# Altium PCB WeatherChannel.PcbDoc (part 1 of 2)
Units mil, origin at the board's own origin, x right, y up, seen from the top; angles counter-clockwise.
Board outline 4050 x 7300 mil, 2 copper layers (Top Layer, Bottom Layer); 129 components, 144 nets, 770 pads, 170 vias.
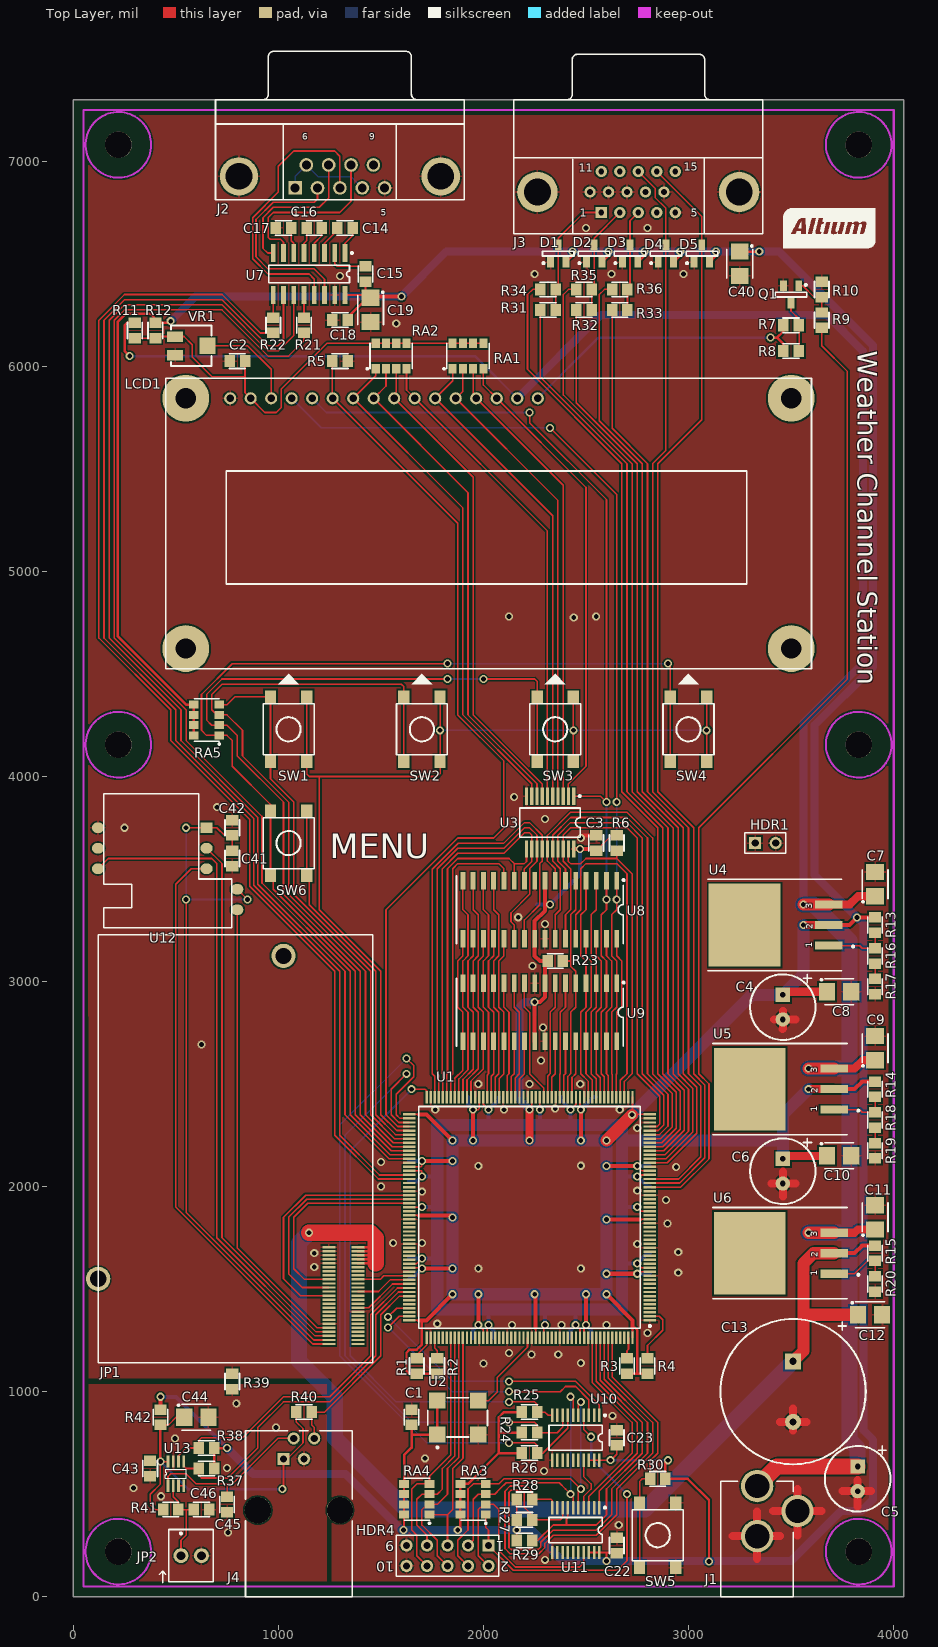
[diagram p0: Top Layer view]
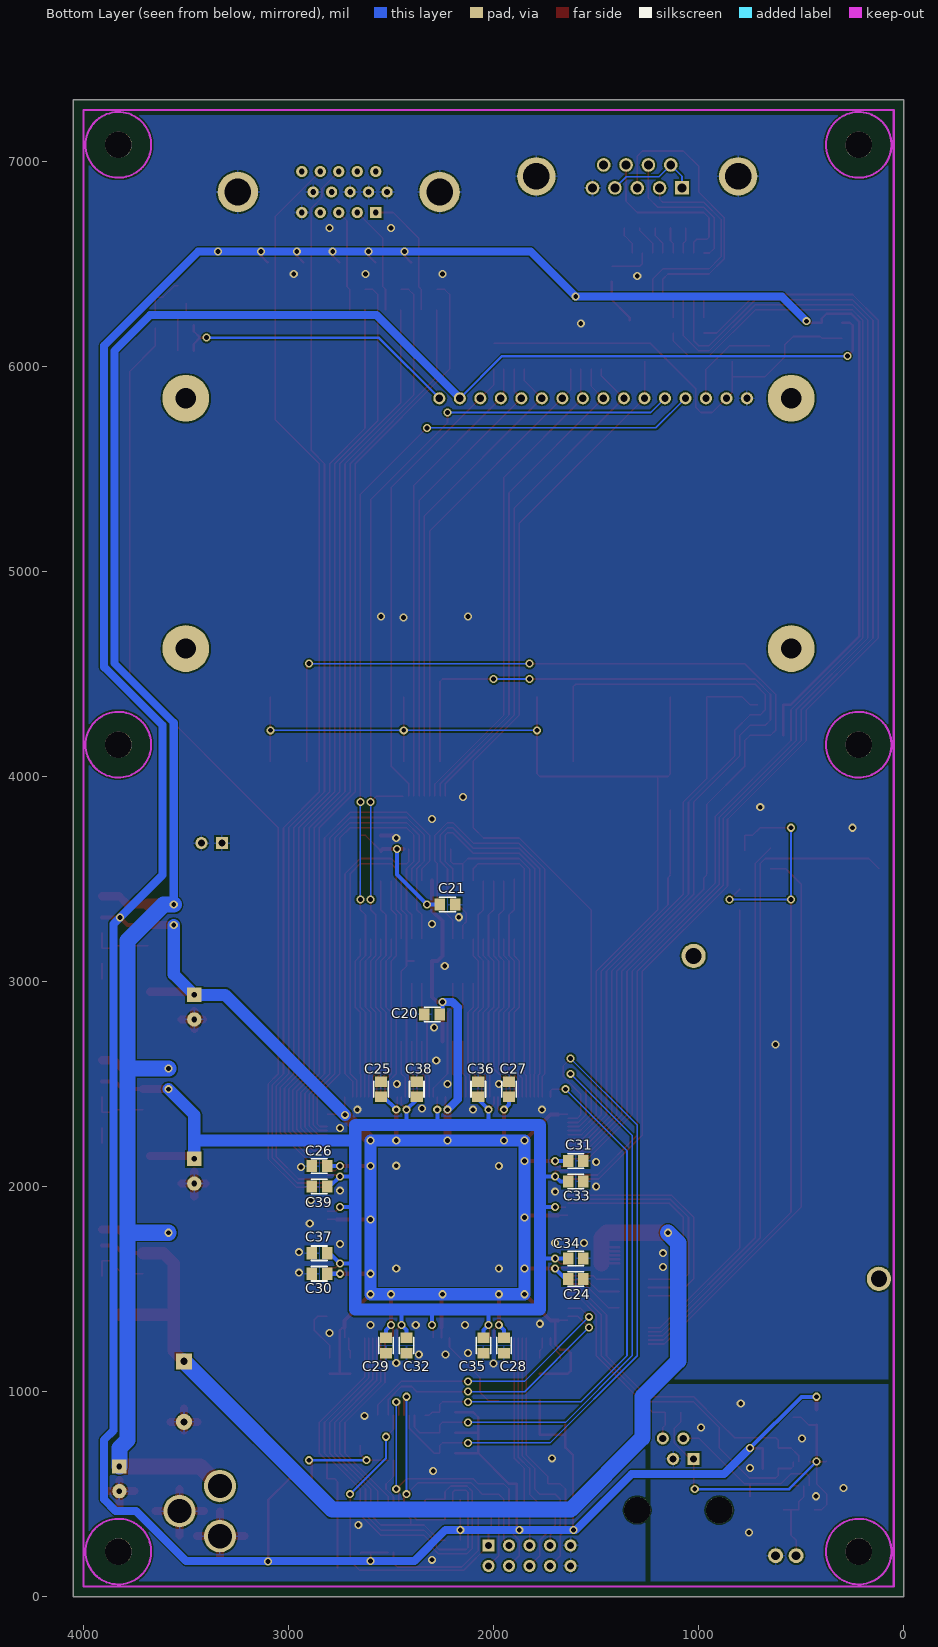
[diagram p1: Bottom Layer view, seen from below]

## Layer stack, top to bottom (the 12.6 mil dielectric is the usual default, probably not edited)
Top Layer: signal copper 1.4
Dielectric: dielectric 12.6, FR-4, Dk 4.8
Bottom Layer: signal copper 1.4

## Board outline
0,0 4050,0 4050,7300 0,7300

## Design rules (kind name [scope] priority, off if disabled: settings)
Clearance [All] p1: gap=7.87
FabricationTestPointUsage TestPointUsage [All] p1: valid=0 allowmultiple=FALSE
FabricationTestpoint Testpoint [All] p1: side=3 testpointundercomponent=TRUE minsize=40 maxsize=100 preferedsize=60 minholesize=0 maxholesize=40 preferedholesize=32 testpointgrid=1 allowsidetop=TRUE allowsidebottom=TRUE usegrid=TRUE gridtolerance=0.01
HoleSize [All] p1: absolutevalues=TRUE maxlimit=157.48 minlimit=1 maxpercent=80.000 minpercent=20.000
PolygonConnect [All] p1: connectstyle=Relief reliefconductorwidth=10 reliefentries=4 polygonreliefangle="90 Angle"
RoomDefinition U_WC_MODEM [InComponentClass('U_WC_MODEM')] p1: confinementstyle=ConfineIn formatcopy=TRUE lockcomponents=FALSE outline 50,1050 1525,1050 1525,4050 50,4050
RoomDefinition FPGA_U1_Manual [InComponentClass('FPGA_U1_Manual')] p2: confinementstyle=ConfineIn formatcopy=TRUE lockcomponents=FALSE outline 1450,625 2900,625 2900,1325 1450,1325
RoomDefinition U_FPGA_U1_Auto [InComponentClass('U_FPGA_U1_Auto')] p3: confinementstyle=ConfineIn formatcopy=TRUE lockcomponents=FALSE outline 1580,1160 2860,1160 2860,2540 1580,2540
RoomDefinition U_WC_Boot [InComponentClass('U_WC_Boot')] p4: confinementstyle=ConfineIn formatcopy=TRUE lockcomponents=FALSE outline 1450,1025 1450,25 2850,25 2850,1025
RoomDefinition U_WC_KB [InComponentClass('U_WC_KB')] p5: confinementstyle=ConfineIn formatcopy=TRUE lockcomponents=FALSE outline 50,3450 3250,3450 3250,4455 50,4455
RoomDefinition U_WC_LCD [InComponentClass('U_WC_LCD')] p6: confinementstyle=ConfineIn formatcopy=TRUE lockcomponents=FALSE outline 100,3550 4100,3550 4100,6525 100,6525
RoomDefinition U_WC_PWR [InComponentClass('U_WC_PWR')] p7: confinementstyle=ConfineIn formatcopy=TRUE lockcomponents=FALSE outline 4125,-200 4125,3850 3085,3850 3085,-200
RoomDefinition U_WC_RS232 [InComponentClass('U_WC_RS232')] p8: confinementstyle=ConfineIn formatcopy=TRUE lockcomponents=FALSE outline 2025,7625 350,7625 350,6100 2025,6100
RoomDefinition U_WC_SENS [InComponentClass('U_WC_SENS')] p9: confinementstyle=ConfineIn formatcopy=TRUE lockcomponents=FALSE outline 325,-25 1425,-25 1425,1125 325,1125
RoomDefinition U_WC_SRAM [InComponentClass('U_WC_SRAM')] p10: confinementstyle=ConfineIn formatcopy=TRUE lockcomponents=FALSE outline 2850,2550 2850,3550 1750,3550 1750,2550
RoomDefinition U_WC_VGA [InComponentClass('U_WC_VGA')] p11: confinementstyle=ConfineIn formatcopy=TRUE lockcomponents=FALSE outline 3375,7575 2065,7575 2065,6150 3375,6150
RoutingVias [All] p1: holewidth=23.62 width=39.37 viastyle="Through Hole" minholewidth=23.62 minwidth=39.37 maxholewidth=23.62 maxwidth=39.37
SilkscreenOverComponentPads [All] p1: minsilkscreentomaskgap=10
SolderMaskExpansion [All] p1: expansion=4
Width Width_Power [(InNet('1V8') OR InNet('4V1') OR InNet('VCC') OR InNet('5V') OR InNet('GND'))] p1: maxlimit=98.43 minlimit=7.87 preferedwidth=7.87
Width [All] p2: maxlimit=11.81 minlimit=7.87 preferedwidth=7.87
24 further rules are at their usual default settings.

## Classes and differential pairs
component class U_WC_Boot: C22 C23 HDR4 R24 R25 R26 R27 R28 R29 RA3 RA4 U10 U11
component class U_FPGA_U1_Auto: U1
net class RED[1..0]: RED0 RED1
net class RAM_ADDR[16..0]: RAM_ADDR0 RAM_ADDR1 RAM_ADDR2 RAM_ADDR3 RAM_ADDR4 RAM_ADDR5 RAM_ADDR6 RAM_ADDR7 RAM_ADDR8 RAM_ADDR9 RAM_ADDR10 RAM_ADDR11 RAM_ADDR12 RAM_ADDR13 RAM_ADDR14 RAM_ADDR15 RAM_ADDR16
net class RAM1_DATA[7..0]: RAM1_DATA0 RAM1_DATA1 RAM1_DATA2 RAM1_DATA3 RAM1_DATA4 RAM1_DATA5 RAM1_DATA6 RAM1_DATA7
net class RAM0_DATA[7..0]: RAM0_DATA0 RAM0_DATA1 RAM0_DATA2 RAM0_DATA3 RAM0_DATA4 RAM0_DATA5 RAM0_DATA6 RAM0_DATA7
net class KP_ROW[3..0]: KP_ROW0 KP_ROW1 KP_ROW2 KP_ROW3
net class KP_COL[3..0]: KP_COL0 KP_COL1 KP_COL2 KP_COL3
net class GREEN[1..0]: GREEN0 GREEN1
net class BLUE[1..0]: BLUE0 BLUE1
component class U_WC_VGA: C40 D1 D2 D3 D4 D5 J3 R31 R32 R33 R34 R35 R36
component class U_WC_SRAM: C20 C21 R23 U8 U9
component class U_WC_SENS: C43 C44 C45 C46 J4 JP2 R37 R38 R39 R40 R41 R42 U13
component class U_WC_RS232: C14 C15 C16 C17 C18 C19 J2 R21 R22 U7
component class U_WC_PWR: C4 C5 C6 C7 C8 C9 C10 C11 C12 C13 HDR1 J1 R13 R14 R15 R16 R17 R18 R19 R20 U4 U5 U6
component class U_WC_MODEM: C41 C42 JP1 U12
component class U_WC_KB: RA5 SW1 SW2 SW3 SW4 SW6
component class FPGA_U1_Manual: C1 R1 R2 R3 R4 U2
component class U_WC_LCD: C2 C3 LCD1 Q1 R5 R6 R7 R8 R9 R10 R11 R12 RA1 RA2 U3 VR1

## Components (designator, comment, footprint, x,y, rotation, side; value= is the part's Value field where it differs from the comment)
C1 "0.1uF" CC2012-0805 1650,875 r90 top
C2 "0.1uF" CC2012-0805 800,6025 r180 top
C3 "0.1uF" CC2012-0805 2550,3675 r90 top
C4 "470uF 16V" RB8/3.5 3460,2875 r0 top
C5 "470uF 16V" RB8/3.5 3825,575 r0 top
C6 "470uF 16V" RB8/3.5 3460,2075 r0 top
C7 "10uF" MCCT-B 3910,3475 r90 top
C8 "10uF" MCCT-B 3735,2950 r0 top
C9 "10uF" MCCT-B 3910,2675 r90 top
C10 "10uF" MCCT-B 3735,2150 r0 top
C11 "10uF" MCCT-B 3910,1850 r90 top
C12 "10uF" MCCT-B 3885,1375 r0 top
C13 "10000uF 16V" RB18/7.5 3510,1000 r0 top
C14 "0.1uF" CC2012-0805 1325,6675 r180 top
C15 "0.1uF" CC2012-0805 1425,6450 r90 top
C16 "0.1uF" CC2012-0805 1175,6675 r180 top
C17 "0.1uF" CC2012-0805 1025,6675 r180 top
C18 "0.1uF" CC2012-0805 1300,6225 r180 top
C19 "10uF" MCCT-B 1450,6275 r270 top
C20 "0.1uF" CC2012-0805 2300,2840 r0 bottom
C21 "0.1uF" CC2012-0805 2225,3375 r180 bottom
C22 "0.1uF" CC2012-0805 2650,250 r270 top
C23 "0.1uF" CC2012-0805 2650,775 r270 top
C24 "0.1uF" CC2012-0805 1600,1550 r180 bottom
C25 "0.1uF" CC2012-0805 2550,2475 r90 bottom
C26 "0.1uF" CC2012-0805 2850,2100 r0 bottom
C27 "0.1uF" CC2012-0805 1925,2475 r90 bottom
C28 "0.1uF" CC2012-0805 1950,1225 r270 bottom
C29 "0.1uF" CC2012-0805 2525,1225 r270 bottom
C30 "0.1uF" CC2012-0805 2850,1575 r0 bottom
C31 "0.1uF" CC2012-0805 1600,2125 r180 bottom
C32 "0.1uF" CC2012-0805 2425,1225 r270 bottom
C33 "0.1uF" CC2012-0805 1600,2025 r180 bottom
C34 "0.1uF" CC2012-0805 1600,1650 r180 bottom
C35 "0.1uF" CC2012-0805 2050,1225 r270 bottom
C36 "0.1uF" CC2012-0805 2075,2475 r90 bottom
C37 "0.1uF" CC2012-0805 2850,1675 r0 bottom
C38 "0.1uF" CC2012-0805 2375,2475 r90 bottom
C39 "0.1uF" CC2012-0805 2850,2000 r0 bottom
C40 "10uF" MCCT-B 3250,6500 r270 top
C41 "0.1uF" CC2012-0805 775,3600 r270 top
C42 "0.1uF" CC2012-0805 775,3750 r90 top
C43 "0.1uF" CC2012-0805 375,625 r270 top
C44 "10uF" MCCT-B 600,875 r0 top
C45 "100pF" CC2012-0805 750,450 r270 top
C46 "100pF" CC2012-0805 625,425 r0 top
D1 "BAS40-04" SO-G3 2365,6550 r0 top
D2 "BAS40-04" SO-G3 2540,6550 r0 top
D3 "BAS40-04" SO-G3 2715,6550 r0 top
D4 "BAS40-04" SO-G3 2890,6550 r0 top
D5 "BAS40-04" SO-G3 3065,6550 r0 top
HDR1 "Header 2" HDR1X2 3325,3675 r0 top
HDR4 "Header 5X2" HDR2X5 2025,250 r180 top
J1 "PWR2.5" PWR2.5 3335,0 r90 top
J2 "DB9 Female" DSUB1.385-2H9 1300,7300 r0 top
J3 "Dsub-15-Female-HD" DB15-VGA-Female 2575,6750 r0 top
J4 "95009-2641" JACK1.27-2H4D 1100,0 r0 top
JP1 "Header 25X2" MC45 1025,3125 r180 top
JP2 "MHDR1X2" TS2.54x2 525,200 r90 top
LCD1 "162A" 162A 450,4525 r0 top
Q1 "2N7002" SO-G3 3500,6350 r180 top
R1 "4K7" CC2012-0805 1675,1125 r90 top
R2 "4K7" CC2012-0805 1775,1125 r90 top
R3 "4K7" CC2012-0805 2700,1125 r90 top
R4 "4K7" CC2012-0805 2800,1125 r90 top
R5 "4K7" CC2012-0805 1300,6025 r0 top
R6 "1K" CC2012-0805 2650,3675 r90 top
R7 "68R" CC2012-0805 3500,6200 r0 top
R8 "68R" CC2012-0805 3500,6075 r0 top
R9 "560R" CC2012-0805 3650,6225 r90 top
R10 "10K" CC2012-0805 3650,6375 r270 top
R11 "0R" CC2012-0805 300,6175 r270 top
R12 "0R" CC2012-0805 400,6175 r270 top
R13 "120R" CC2012-0805 3910,3275 r270 top
R14 "120R" CC2012-0805 3910,2475 r270 top
R15 "120R" CC2012-0805 3910,1675 r270 top
R16 "100R" CC2012-0805 3910,3125 r270 top
R17 "100R" CC2012-0805 3910,2975 r270 top
R18 "47R" CC2012-0805 3910,2325 r270 top
R19 "5R6" CC2012-0805 3910,2175 r270 top
R20 "270R" CC2012-0805 3910,1525 r270 top
R21 "100R" CC2012-0805 1125,6200 r90 top
R22 "100R" CC2012-0805 975,6200 r90 top
R23 "4K7" CC2012-0805 2350,3100 r0 top
R24 "4K7" CC2012-0805 2225,800 r0 top
R25 "4K7" CC2012-0805 2225,900 r0 top
R26 "4K7" CC2012-0805 2225,700 r0 top
R27 "4K7" CC2012-0805 2200,375 r0 top
R28 "4K7" CC2012-0805 2200,475 r0 top
R29 "4K7" CC2012-0805 2200,275 r0 top
R30 "4K7" CC2012-0805 2850,575 r180 top
R31 "680R" CC2012-0805 2315,6275 r0 top
R32 "680R" CC2012-0805 2490,6275 r0 top
R33 "680R" CC2012-0805 2665,6275 r0 top
R34 "330R" CC2012-0805 2315,6375 r0 top
R35 "330R" CC2012-0805 2490,6375 r0 top
R36 "330R" CC2012-0805 2665,6375 r0 top
R37 "4K7" CC2012-0805 650,625 r180 top
R38 "4K7" CC2012-0805 650,725 r180 top
R39 "0R" CC2012-0805 775,1050 r270 top
R40 "2K7" CC2012-0805 1125,900 r0 top
R41 "2K7" CC2012-0805 475,425 r0 top
R42 "4R7" CC2012-0805 425,875 r270 top
RA1 "4K7" MNR34 1925,6050 r90 top
RA2 "4K7" MNR34 1550,6050 r90 top
RA3 "4K7" MNR34 1950,475 r180 top
RA4 "4K7" MNR34 1675,475 r180 top
RA5 "4K7" MNR34 650,4275 r180 top
SW1 "B3FS" B3FS_SWITCH 1050,4230 r90 top
SW2 "B3FS" B3FS_SWITCH 1700,4230 r90 top
SW3 "B3FS" B3FS_SWITCH 2350,4230 r90 top
SW4 "B3FS" B3FS_SWITCH 3000,4230 r90 top
SW5 "B3FS" B3FS_SWITCH 2850,300 r270 top
SW6 "B3FS" B3FS_SWITCH 1050,3675 r90 top
U1 "XC2S300E-6PQ208C" PQ208 2225,1850 r180 top
U2 "QSMO_4200" QSMO_4200 1775,775 r0 top
U3 "74LVC245A" SSO-G20/P.65 2325,3775 r180 top
U4 "LM1084IS-ADJ" TO-263 3685,3175 r90 top
U5 "LM1084IS-ADJ" TO-263 3710,2375 r90 top
U6 "LM1084IS-ADJ" TO-263 3710,1575 r90 top
U7 "MAX3232EUE" SO-G16 1150,6450 r180 top
U8 "IDT71V124SA15Y" SO-J32 2275,3350 r180 top
U9 "IDT71V124SA15Y" SO-J32 2275,2850 r180 top
U10 "XCF01SVO20C" VO20 2450,775 r180 top
U11 "XCF01SVO20C" VO20 2450,325 r180 top
U12 "CCM03_CARD_SOCKET" CCM03_MKIII 650,3750 r0 top
U13 "MAX1037" SOT23_8 500,600 r90 top
VR1 "20K" POT4MM-2 575,6100 r0 top
? "" AltiumLogo48mm 3457.86,6575 r0 top

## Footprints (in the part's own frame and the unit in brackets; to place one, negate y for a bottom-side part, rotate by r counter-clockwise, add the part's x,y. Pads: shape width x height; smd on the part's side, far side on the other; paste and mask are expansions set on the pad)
162A [mm]
  round 1.5 hole 0.9: 1(8.001,33.503) 2(10.541,33.503) 3(13.081,33.503) 4(15.621,33.503) 5(18.161,33.503) 6(20.701,33.503) 7(23.241,33.503) 8(25.781,33.503) 9(28.321,33.503) 10(30.861,33.503) 11(33.401,33.503) 12(35.941,33.503) 13(38.481,33.503) 14(41.021,33.503) 15(43.561,33.503) 16(46.101,33.503)
  round 5.8 hole 2.5 unplated: M1(2.501,33.503) M2(77.501,33.503) M3(2.501,2.503) M4(77.501,2.503)
  silkscreen extent 0,0 80,36
AltiumLogo48mm [mil]
  silkscreen extent 4,4 452,196
B3FS_SWITCH [mm]
  rect 1.6x1.4 smd: 1(4.01,-2.25) 2(-4,-2.25) 3(4.01,2.24) 4(-4,2.24)
  silkscreen extent -3.16,-3.16 3.15,3.15
CC2012-0805 [mm]
  rect 1.3x1.5 smd: 1(-0.95,0) 2(0.95,0)
  silkscreen extent -1,-0.9 1,0.9
CCM03_MKIII [mm] "SIM/SAM card connector with card detection switch"
  rect 1.5x1.3 smd: 1(0,0)
  oval 1.5x1.3 smd: 2(0,-2.54) 3(0,-5.08) 4(-13.45,0) 5(-13.45,-2.54) 6(-13.45,-5.08) 7(3.8,-7.62) 8(3.8,-10.16)
  silkscreen extent -12.75,-12.4 3.1,4.2
DB15-VGA-Female [mm]
  rect 1.4x1.4 hole 0.7: 1(0,0)
  round 1.4 hole 0.7: 2(2.29,0) 3(4.58,0) 4(6.87,0) 5(9.16,0) 6(-1.4,2.54) 7(0.89,2.54) 8(3.18,2.54) 9(5.47,2.54) 10(7.76,2.54) 11(0,5.08) 12(2.29,5.08) 13(4.58,5.08) 14(6.87,5.08) 15(9.16,5.08)
  round 5 hole 3.3: 16(-7.915,2.54) 17(17.075,2.54)
  silkscreen extent -10.83,-2.65 20.01,19.61
DSUB1.385-2H9 [mm]
  rect 1.69x1.69 hole 1.1: 1(-5.54,-10.92)
  round 1.69 hole 1.1: 2(-2.77,-10.92) 3(0,-10.92) 4(2.77,-10.92) 5(5.54,-10.92) 6(-4.155,-8.08) 7(-1.385,-8.08) 8(1.385,-8.08) 9(4.155,-8.08)
  round 4.76 hole 3.3: 10(-12.495,-9.5) 11(12.495,-9.5)
  silkscreen extent -15.4,-12.4 15.4,6
HDR1X2 [mm]
  rect 1.5x1.5 hole 0.9: 1(0,0)
  round 1.5 hole 0.9: 2(2.54,0)
  silkscreen extent -1.27,-1.27 3.81,1.27
HDR2X5 [mm]
  rect 1.5x1.5 hole 0.9: 1(0,0)
  round 1.5 hole 0.9: 2(0,2.54) 3(2.54,0) 4(2.54,2.54) 5(5.08,0) 6(5.08,2.54) 7(7.62,0) 8(7.62,2.54) 9(10.16,0) 10(10.16,2.54)
  silkscreen extent -1.27,-1.27 11.43,3.81
JACK1.27-2H4D [mm] "Connector; PCB Jack, Thru-Hole; 1-Port, 6 Positions, 4 Loaded; Unshielded without Lightpipes; Right Angle"
  rect 1.5x1.5 hole 0.9: 1(-1.905,17.07)
  round 1.5 hole 0.9: 2(-0.635,19.61) 3(0.635,17.07) 4(1.905,19.61)
  round 3.25 hole 3.25: MH1(-5.08,10.72) MH2(5.08,10.72)
  silkscreen extent -6.6,0 6.61,20.57
MC45 [mm]
  round 3 hole 2: 0(0,0) 0(22.95,40)
  rect 1.6x0.3 smd: 1(-5.625,48.075) 2(-5.625,47.575) 3(-5.625,47.075) 4(-5.625,46.575) 5(-5.625,46.075) 6(-5.625,45.575) 7(-5.625,45.075) 8(-5.625,44.575) 9(-5.625,44.075) 10(-5.625,43.575) 11(-5.625,43.075) 12(-5.625,42.575) 13(-5.625,42.075) 14(-5.625,41.575) 15(-5.625,41.075) 16(-5.625,40.575) 17(-5.625,40.075) 18(-5.625,39.575) 19(-5.625,39.075) 20(-5.625,38.575) 21(-5.625,38.075) 22(-5.625,37.575) 23(-5.625,37.075) 24(-5.625,36.575) 25(-5.625,36.075) 26(-9.225,36.075) 27(-9.225,36.575) 28(-9.225,37.075) 29(-9.225,37.575) 30(-9.225,38.075) 31(-9.225,38.575) 32(-9.225,39.075) 33(-9.225,39.575) 34(-9.225,40.075) 35(-9.225,40.575) 36(-9.225,41.075) 37(-9.225,41.575) 38(-9.225,42.075) 39(-9.225,42.575) 40(-9.225,43.075) 41(-9.225,43.575) 42(-9.225,44.075) 43(-9.225,44.575) 44(-9.225,45.075) 45(-9.225,45.575) 46(-9.225,46.075) 47(-9.225,46.575) 48(-9.225,47.075) 49(-9.225,47.575) 50(-9.225,48.075)
  silkscreen extent -11.05,-2.62 22.95,50.4
MCCT-B [mm]
  rect 2x2.2 smd: 1(-1.5,0) 2(1.5,0)
  silkscreen extent -2.3,-1.6 1.8,1.6
MNR34 [mm]
  rect 1.2x1 smd: 1(-1.575,1.905) 2(-1.575,0.635) 3(-1.575,-0.635) 4(-1.575,-1.905) 5(1.575,-1.905) 6(1.575,-0.635) 7(1.575,0.635) 8(1.575,1.905)
  silkscreen extent -1.67,-2.62 1.55,3.07
POT4MM-2 [mm]
  rect 2x1.3 smd: CCW(-2,-1.15) CW(-2,1.15)
  rect 2x2 smd: W(2,0)
  silkscreen extent -2.5,-2.5 2.5,2.5
PQ208 [mm] "208-Pin Plastic Quad Flat Pack (PQ208)"
  rect 1.55x0.3 smd: 1(-14.9,12.75) 2(-14.9,12.25) 3(-14.9,11.75) 4(-14.9,11.25) 5(-14.9,10.75) 6(-14.9,10.25) 7(-14.9,9.75) 8(-14.9,9.25) 9(-14.9,8.75) 10(-14.9,8.25) 11(-14.9,7.75) 12(-14.9,7.25) 13(-14.9,6.75) 14(-14.9,6.25) 15(-14.9,5.75) 16(-14.9,5.25) 17(-14.9,4.75) 18(-14.9,4.25) 19(-14.9,3.75) 20(-14.9,3.25) 21(-14.9,2.75) 22(-14.9,2.25) 23(-14.9,1.75) 24(-14.9,1.25) 25(-14.9,0.75) 26(-14.9,0.25) 27(-14.9,-0.25) 28(-14.9,-0.75) 29(-14.9,-1.25) 30(-14.9,-1.75) 31(-14.9,-2.25) 32(-14.9,-2.75) 33(-14.9,-3.25) 34(-14.9,-3.75) 35(-14.9,-4.25) 36(-14.9,-4.75) 37(-14.9,-5.25) 38(-14.9,-5.75) 39(-14.9,-6.25) 40(-14.9,-6.75) 41(-14.9,-7.25) 42(-14.9,-7.75) 43(-14.9,-8.25) 44(-14.9,-8.75) 45(-14.9,-9.25) 46(-14.9,-9.75) 47(-14.9,-10.25) 48(-14.9,-10.75) 49(-14.9,-11.25) 50(-14.9,-11.75) 51(-14.9,-12.25) 52(-14.9,-12.75) 105(14.9,-12.75) 106(14.9,-12.25) 107(14.9,-11.75) 108(14.9,-11.25) 109(14.9,-10.75) 110(14.9,-10.25) 111(14.9,-9.75) 112(14.9,-9.25) 113(14.9,-8.75) 114(14.9,-8.25) 115(14.9,-7.75) 116(14.9,-7.25) 117(14.9,-6.75) 118(14.9,-6.25) 119(14.9,-5.75) 120(14.9,-5.25) 121(14.9,-4.75) 122(14.9,-4.25) 123(14.9,-3.75) 124(14.9,-3.25) 125(14.9,-2.75) 126(14.9,-2.25) 127(14.9,-1.75) 128(14.9,-1.25) 129(14.9,-0.75) 130(14.9,-0.25) 131(14.9,0.25) 132(14.9,0.75) 133(14.9,1.25) 134(14.9,1.75) 135(14.9,2.25) 136(14.9,2.75) 137(14.9,3.25) 138(14.9,3.75) 139(14.9,4.25) 140(14.9,4.75) 141(14.9,5.25) 142(14.9,5.75) 143(14.9,6.25) 144(14.9,6.75) 145(14.9,7.25) 146(14.9,7.75) 147(14.9,8.25) 148(14.9,8.75) 149(14.9,9.25) 150(14.9,9.75) 151(14.9,10.25) 152(14.9,10.75) 153(14.9,11.25) 154(14.9,11.75) 155(14.9,12.25) 156(14.9,12.75)
  rect 0.3x1.55 smd: 53(-12.75,-14.9) 54(-12.25,-14.9) 55(-11.75,-14.9) 56(-11.25,-14.9) 57(-10.75,-14.9) 58(-10.25,-14.9) 59(-9.75,-14.9) 60(-9.25,-14.9) 61(-8.75,-14.9) 62(-8.25,-14.9) 63(-7.75,-14.9) 64(-7.25,-14.9) 65(-6.75,-14.9) 66(-6.25,-14.9) 67(-5.75,-14.9) 68(-5.25,-14.9) 69(-4.75,-14.9) 70(-4.25,-14.9) 71(-3.75,-14.9) 72(-3.25,-14.9) 73(-2.75,-14.9) 74(-2.25,-14.9) 75(-1.75,-14.9) 76(-1.25,-14.9) 77(-0.75,-14.9) 78(-0.25,-14.9) 79(0.25,-14.9) 80(0.75,-14.9) 81(1.25,-14.9) 82(1.75,-14.9) 83(2.25,-14.9) 84(2.75,-14.9) 85(3.25,-14.9) 86(3.75,-14.9) 87(4.25,-14.9) 88(4.75,-14.9) 89(5.25,-14.9) 90(5.75,-14.9) 91(6.25,-14.9) 92(6.75,-14.9) 93(7.25,-14.9) 94(7.75,-14.9) 95(8.25,-14.9) 96(8.75,-14.9) 97(9.25,-14.9) 98(9.75,-14.9) 99(10.25,-14.9) 100(10.75,-14.9) 101(11.25,-14.9) 102(11.75,-14.9) 103(12.25,-14.9) 104(12.75,-14.9) 157(12.75,14.9) 158(12.25,14.9) 159(11.75,14.9) 160(11.25,14.9) 161(10.75,14.9) 162(10.25,14.9) 163(9.75,14.9) 164(9.25,14.9) 165(8.75,14.9) 166(8.25,14.9) 167(7.75,14.9) 168(7.25,14.9) 169(6.75,14.9) 170(6.25,14.9) 171(5.75,14.9) 172(5.25,14.9) 173(4.75,14.9) 174(4.25,14.9) 175(3.75,14.9) 176(3.25,14.9) 177(2.75,14.9) 178(2.25,14.9) 179(1.75,14.9) 180(1.25,14.9) 181(0.75,14.9) 182(0.25,14.9) 183(-0.25,14.9) 184(-0.75,14.9) 185(-1.25,14.9) 186(-1.75,14.9) 187(-2.25,14.9) 188(-2.75,14.9) 189(-3.25,14.9) 190(-3.75,14.9) 191(-4.25,14.9) 192(-4.75,14.9) 193(-5.25,14.9) 194(-5.75,14.9) 195(-6.25,14.9) 196(-6.75,14.9) 197(-7.25,14.9) 198(-7.75,14.9) 199(-8.25,14.9) 200(-8.75,14.9) 201(-9.25,14.9) 202(-9.75,14.9) 203(-10.25,14.9) 204(-10.75,14.9) 205(-11.25,14.9) 206(-11.75,14.9) 207(-12.25,14.9) 208(-12.75,14.9)
  silkscreen extent -15.03,-13.72 13.72,13.72
PWR2.5 [mm]
  round 4 hole 3: 1(13.7,0) 2(10.6,-5) 3(7.5,0)
  silkscreen extent 0,-4.48 14.3,4.5
QSMO_4200 [mm]
  rect 2x2 smd: 1(0,0.4) 2(5.08,0.4) 3(5.08,4.6) 4(0,4.6)
  silkscreen extent -1.19,-1.31 6.22,4.95
RB8/3.5 [mil]
  rect 70x70 hole 27.56: 1(0,60)
  round 70 hole 27.56: 2(0,-60)
  silkscreen extent -160,-160 160,160
RB18/7.5 [mm]
  rect 2x2 hole 0.9: 1(0,3.75)
  round 2 hole 0.9: 2(0,-3.75)
  silkscreen extent -9,-9 9,9
SO-G3 [mm]
  rect 0.85x1.3 smd: 1(-0.95,-1.1) 2(0.95,-1.1) 3(0,1.1)
  silkscreen extent -1.95,-1.32 1.95,0.3
SO-G16 [mm]
  rect 0.6x2.2 smd: 1(-4.445,-2.6) 2(-3.175,-2.6) 3(-1.905,-2.6) 4(-0.635,-2.6) 5(0.635,-2.6) 6(1.905,-2.6) 7(3.175,-2.6) 8(4.445,-2.6) 9(4.445,2.6) 10(3.175,2.6) 11(1.905,2.6) 12(0.635,2.6) 13(-0.635,2.6) 14(-1.905,2.6) 15(-3.175,2.6) 16(-4.445,2.6)
  silkscreen extent -5.42,-2.72 5,1.1
SO-J32 [mm]
  rect 0.6x2.2 smd: 1(-9.525,-3.6) 2(-8.255,-3.6) 3(-6.985,-3.6) 4(-5.715,-3.6) 5(-4.445,-3.6) 6(-3.175,-3.6) 7(-1.905,-3.6) 8(-0.635,-3.6) 9(0.635,-3.6) 10(1.905,-3.6) 11(3.175,-3.6) 12(4.445,-3.6) 13(5.715,-3.6) 14(6.985,-3.6) 15(8.255,-3.6) 16(9.525,-3.6) 17(9.525,3.6) 18(8.255,3.6) 19(6.985,3.6) 20(5.715,3.6) 21(4.445,3.6) 22(3.175,3.6) 23(1.905,3.6) 24(0.635,3.6) 25(-0.635,3.6) 26(-1.905,3.6) 27(-3.175,3.6) 28(-4.445,3.6) 29(-5.715,3.6) 30(-6.985,3.6) 31(-8.255,3.6) 32(-9.525,3.6)
  silkscreen extent -10.5,-4.19 10.32,4.19
SOT23_8 [mm]
  rect 1.5x0.35 smd: 1(-1.5,0.975) 2(-1.5,0.325) 3(-1.5,-0.325) 4(-1.5,-0.975) 5(1.5,-0.975) 6(1.5,-0.325) 7(1.5,0.325) 8(1.5,0.975)
  silkscreen extent -0.55,-1.3 0.55,1.3
SSO-G20/P.65 [mm]
  rect 0.4x2.15 smd: 1(-2.925,-3.275) 2(-2.275,-3.275) 3(-1.625,-3.275) 4(-0.975,-3.275) 5(-0.325,-3.275) 6(0.325,-3.275) 7(0.975,-3.275) 8(1.625,-3.275) 9(2.275,-3.275) 10(2.925,-3.275) 11(2.925,3.275) 12(2.275,3.275) 13(1.625,3.275) 14(0.975,3.275) 15(0.325,3.275) 16(-0.325,3.275) 17(-0.975,3.275) 18(-1.625,3.275) 19(-2.275,3.275) 20(-2.925,3.275)
  silkscreen extent -3.8,-3.4 3.75,1.8
TO-263 [mm]
  rect 1x3.4 smd: 1(0,0) 2(2.54,0) 3(5.08,0)
  rect 10.25x8.9 smd: 4(2.54,10.45)
  silkscreen extent -3.1,-3.13 8.2,15
TS2.54x2 [mm]
  round 1.85 hole 1.1: 1(0,0) 2(0,-2.54)
  silkscreen extent -3.35,-4 3.25,2.65
VO20 [mm]
  rect 0.3x1.65 smd: 1(-2.925,-2.775) 2(-2.275,-2.775) 3(-1.625,-2.775) 4(-0.975,-2.775) 5(-0.325,-2.775) 6(0.325,-2.775) 7(0.975,-2.775) 8(1.625,-2.775) 9(2.275,-2.775) 10(2.925,-2.775) 11(2.925,2.775) 12(2.275,2.775) 13(1.625,2.775) 14(0.975,2.775) 15(0.325,2.775) 16(-0.325,2.775) 17(-0.975,2.775) 18(-1.625,2.775) 19(-2.275,2.775) 20(-2.925,2.775)
  silkscreen extent -3.75,-2.9 3.3,1.55

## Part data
C1 C2 C3 C14 C15 C16 C17 C18 C20 C21 C22 C23 C24 C25 C26 C27 C28 C29 C30 C31 C32 C33 C34 C35 C36 C37 C38 C39 C41 C42 C43 C45 C46: library part CAP, "Capacitor"
C4 C5 C6 C7 C8 C9 C10 C11 C12 C13 C19 C40 C44: library part CAP_POLAR, "Polar Capacitor"
D1 D2 D3 D4 D5: "Shottky Diode Pair"
HDR1 JP2: "Header, 2-Pin"
HDR4: "Header, 5-Pin, Dual row"
J1: "Low Voltage Power Supply Sonnector"
J2: library part "D Connector 9", "Receptacle Assembly, 9 Position, Right Angle"
J3: "Dsub-15 High density VGA Female connetor"
J4: "Right Angle, Standard Profile, with Mounting Rib, Flush Mount PCB Jack"
JP1: "Header, 25-Pin, Dual row"
LCD1: "16 char * 2 line LCD character display with b/light"
Q1: "N Channel Mosfet"
R1 R2 R3 R4 R5 R6 R7 R8 R9 R10 R11 R12 R13 R14 R15 R16 R17 R18 R19 R20 R21 R22 R23 R24 R25 R26 R27 R28 R29 R30 R31 R32 R33 R34 R35 R36 R37 R38 R39 R40 R41 R42: library part RES, "Resistor"
RA1 RA2 RA3 RA4 RA5: library part MNR34, "3216x4 Resistor Array"
SW1 SW2 SW3 SW4 SW5 SW6: "SPNA SMD Keyboard Switch"
U1: "Spartan-IIE 1.8V FPGA, 208-Pin PQFP, Standard Performance, Commercial Grade"
U2: "Surface Mount Crystal Oscillator"
U3: "Octal Bus Transceiver with 3-State Outputs"
U4 U5 U6: "5A Low Dropout Possitive Regulators"
U7: "3.0V TO 5.5V, Low-Power, up to 1Mbps, True RS-232 Transceiver Using Four 0.1µF External Capacitor"
U8 U9: "128K x 8 bit Fast Static RAM"
U10 U11: "XCF00S Series, Platform Flash In-System Programmable Configuration 3.3V PROM, 1-Megabit, Commercial Grade"
U12: "SIM/SAM card connector with card detection switch"
U13: "4 Channel 8 Bit ADC, I2C interface, 2.7V to 3.6V Supply"
VR1: library part POT_M, "Potentiometer"

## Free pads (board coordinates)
  round 129.92 hole 129.92: MH1(3830,220) MH2(3830,4155) MH3(3830,7080) MH4(220,7080) MH5(220,4155) MH6(220,220)

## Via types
v1: diameter 39.37, hole 23.62, Top Layer to Bottom Layer, 170 vias

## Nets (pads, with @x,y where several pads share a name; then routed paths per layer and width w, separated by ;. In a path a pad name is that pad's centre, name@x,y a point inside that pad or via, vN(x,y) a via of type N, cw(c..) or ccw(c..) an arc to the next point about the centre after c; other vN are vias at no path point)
1V8: C6.1 C10.1 C32.1 C33.1 C34.1 C35.1 C36.1 C37.1 C38.1 C39.1 R14.1 U1.14 U1.28 U1.37 U1.67 U1.76 U1.90 U1.119 U1.128 U1.142 U1.172 U1.186 U1.195 U5.2 | length 7674.6
  Top Layer w7.87: U1.142@1638.39,1623.62 1673.62,1623.62 v1(1700,1650) ; U1.119@1638.39,2076.38 1698.62,2076.38 1700,2075 v1(1700,2050) ; U1.128@1650,1900 v1(1700,1900) ; U1.90@1998.62,2436.61 1998.62,2401.38 v1(2025,2375) ; U1.172@2018.31,1263.39 2018.31,1318.31 v1(2025,1325) ; U1.76@2274.21,2436.61 2274.21,2375.79 v1(2275,2375) ; U1.186@2293.9,1263.39 2293.9,1318.9 v1(2300,1325) ; v1(2425,2375) 2451.38,2401.38 U1.67@2451.38,2436.61 ; v1(2450,1325) 2471.06,1303.94 U1.195@2471.06,1263.39 ; v1(2750,1625) 2771.06,1603.94 U1.14@2811.61,1603.94 ; v1(2750,1900) 2770.47,1879.53 U1.28@2811.61,1879.53 ; v1(2750,2050) 2756.69,2056.69 U1.37@2811.61,2056.69
  Top Layer w19.68: U5.2@3710,2475 3810,2475 3847.4,2512.4 R14.1@3910,2512.4
  Top Layer w39.37: C6.1@3460,2135 3475,2150 C10.1@3675.95,2150 ; v1(3585,2475) U5.2@3710,2475
  Bottom Layer w19.68: C34.1@1637.4,1650 v1(1700,1650) 1775,1650 ; C33.1@1637.4,2025 1675,2025 v1(1700,2050) 1775,2050 ; v1(1700,1900) 1775,1900 ; 2025,1400 v1(2025,1325) 2050,1300 C35.1@2050,1262.4 ; 2025,2300 v1(2025,2375) 2075,2425 C36.1@2075,2437.6 ; 2275,2300 v1(2275,2375) ; v1(2300,1325) 2300,1400 ; C38.1@2375,2437.6 2375,2425 v1(2425,2375) 2425,2300 ; C32.1@2425,1262.4 2425,1300 v1(2450,1325) 2450,1400 ; 2675,1625 v1(2750,1625) 2800,1675 C37.1@2812.6,1675 ; 2675,1900 v1(2750,1900) ; 2675,2050 v1(2750,2050) 2800,2000 C39.1@2812.6,2000
  Bottom Layer w59.06: 2675,2225 3460,2225 ; C6.1@3460,2135 3460,2350 v1(3585,2475) ; 1775,1400 2675,1400 2675,2300 1775,2300 1775,1400
4V1: C12.1 C13.1 JP1.26 JP1.27 JP1.28 JP1.29 JP1.30 R15.1 U6.2 | length 5787.4
  Top Layer w11.81: JP1.30@1388.19,1625.98 1474.02,1625.98 ; JP1.29@1388.19,1645.67 1470.67,1645.67 ; JP1.28@1388.19,1665.35 1465.35,1665.35 ; JP1.27@1388.19,1685.04 1464.96,1685.04 ; JP1.26@1388.19,1704.72 1470.28,1704.72
  Top Layer w19.68: U6.2@3710,1675 3810,1675 3847.4,1712.4 R15.1@3910,1712.4
  Top Layer w59.06: C13.1@3510,1147.64 3560,1197.64 3560,1625 3610,1675 U6.2@3710,1675 ; 3560,1375 C12.1@3825.95,1375
  Top Layer w78.74: v1(1150,1775) 1450,1775 1475,1750 1475,1625
  Bottom Layer w78.74: v1(1150,1775) 1100,1725 1100,1150 1275,975 1275,775 1625,425 2787.36,425 C13.1@3510,1147.64
5V: C5.1 C7.1 C9.1 C11.1 J1.1 LCD1.15 R11.1 U4.3 U5.3 U6.3 | length 11787.8
  Top Layer w11.81: v1(275,6050) 250,6075 250,6200 262.4,6212.4 R11.1@300,6212.4
  Top Layer w39.37: U4.3@3685,3375 3785,3375 ; U6.3@3710,1775 3810,1775 3825.95,1790.95 C11.1@3910,1790.95 ; U5.3@3710,2575 3810,2575 3850.95,2615.95 C9.1@3910,2615.95 ; 3787,3375 3785,3375 ; C7.1@3910,3415.95 3825.95,3415.95 3785,3375
  Top Layer w59.06: v1(3560,3375) U4.3@3685,3375 ; v1(3585,1775) U6.3@3710,1775 ; v1(3585,2575) U5.3@3710,2575
  Top Layer w78.74: J1.1@3335,539.37 3430.63,635 C5.1@3825,635
  Bottom Layer w11.81: v1(275,6050) 1959,6050 LCD1.15@2165,5844
  Bottom Layer w39.37: LCD1.15@2165,5844 2571,6250 3675,6250 3850,6075 3850,4551.86 3560,4261.86 v1(3560,3375)
  Bottom Layer w78.74: v1(3560,3375) 3610,3375 3785,3200 3785,765 3825,725 C5.1@3825,635 ; v1(3585,1775) 3785,1775 ; v1(3585,2575) 3785,2575
AGND: C43.2 C44.2 C45.2 C46.2 J4.3 JP2.2 R39.2 U13.7 | length 22
  Top Layer w7.87: v1(495.66,770.74) v1@495.66,775 ; J4.3@1125,672.05 J4.3@1127.95,675
  Bottom Layer w7.87: v1@750,625 v1(750,627.95) ; v1(989.36,825) v1@1000,825
  other v1: 755,313.77 428.34,490 293.7,530 795,942.12
AIN0: C45.1 J4.2 U13.1 | length 839.9
  Top Layer w7.87: U13.1@461.61,540.95 461.61,586.61 475,600 550,600 600,550 775,550 997.05,772.05 J4.2@1075,772.05 ; C45.1@750,487.4 750,550
AIN1: C46.1 JP2.1 R41.2 U13.2 | length 436.9
  Top Layer w7.87: U13.2@487.2,540.95 487.2,487.8 512.4,462.6 R41.2@512.4,425 C46.1@587.6,425 ; JP2.1@525,200 525,275 550,300 550,425
BLUE0: R33.1 U1.40 | length 4474
  Top Layer w7.87: R33.1@2627.6,6275 2627.6,5697.4 2800,5525 2800,5125 2800,3925 2975,3750 2975,2550 3040,2485 3040,2260 2895.75,2115.75 U1.40@2811.61,2115.75
BLUE1: R36.1 U1.41 | length 4608.5
  Top Layer w7.87: R36.1@2627.6,6375 2590,6375 2565,6350 2565,5735 2775,5525 2775,5125 2775,3925 2950,3750 2950,2550 3020,2480 3020,2265 2890.43,2135.43 U1.41@2811.61,2135.43
CCLK: U1.155 U10.3 | length 1347.5
  Top Layer w7.87: v1(1535.43,1313.51) 1589.64,1367.72 U1.155@1638.39,1367.72 ; v1(2125,1000) 2375,1000 2400,1025 2450,1025 2513.98,961.02 U10.3@2513.98,884.25
  Bottom Layer w7.87: v1(1535.43,1313.51) 1848.93,1000 v1(2125,1000)
CCLK_PR: U1.198 U11.3 | length 997.3
  Top Layer w7.87: U11.3@2513.98,434.25 2513.98,488.98 2725,700 2725,850 2530.12,1044.88 U1.198@2530.12,1263.39
CLK_BRD: U1.182 U2.3 | length 436.2
  Top Layer w7.87: U2.3@1975,956.1 2025.19,956.1 2066.53,997.44 2066.53,1067.64 2215.16,1216.27 U1.182@2215.16,1263.39
CTS: J2.7 U7.8 | length 730.8
  Top Layer w7.87: U7.8@975,6552.36 947.64,6552.36 925,6575 925,6725 975,6775 1200,6775 1245.47,6820.47 J2.7@1245.47,6981.89
DIN: U1.153 U10.1 | length 1379.7
  Top Layer w7.87: v1(1535,1365) 1577.09,1407.09 U1.153@1638.39,1407.09 ; v1(2125,1050) 2450,1050 2565.16,934.84 U10.1@2565.16,884.25
  Bottom Layer w7.87: v1(1535,1365) 1850,1050 v1(2125,1050)
DIN_PR: U1.199 U11.1 | length 988.6
  Top Layer w7.87: U1.199@2549.8,1263.39 2549.8,1050.2 2750,850 2750,700 2565.16,515.16 U11.1@2565.16,434.25
DONE: R25.2 U1.104 U10.10 | length 2658.3
  Top Layer w7.87: v1(1650,2475) 1715,2475 1723.03,2466.97 U1.104@1723.03,2436.61 ; v1(2125,950) 2150,950 2250,950 2262.4,937.6 R25.2@2262.4,900 2300,900 2315.75,884.25 U10.10@2334.84,884.25
  Bottom Layer w7.87: v1(1650,2475) 1350,2175 1350,1175 1575,950 v1(2125,950)
DONE_PR: R28.2 U1.202 U11.10 | length 2278.2
  Top Layer w7.87: U11.10@2334.84,434.25 2334.84,470.16 2330,475 R28.2@2237.4,475 2237.4,512.6 2210,540 2130,540 2105,515 2105,235 2130,210 2270,210 2300,240 2300,260 2340,300 2550,300 2650,400 2650,525 2825,700 2825,850 2608.86,1066.14 U1.202@2608.86,1263.39
GND: C1.2 C2.2 C3.2 C4.2 C5.2 C6.2 C7.2 C8.2 C9.2 C10.2 C11.2 C12.2 C13.2 C17.2 C18.2 C19.2 C20.2 C21.2 C22.1 C23.1 C24.2 C25.2 C26.2 C27.2 C28.2 C29.2 C30.2 C31.2 C32.2 C33.2 C34.2 C35.2 C36.2 C37.2 C38.2 C39.2 C40.2 C41.2 C42.2 D1.1 D2.1 D3.1 D4.1 D5.1 HDR1.1 HDR1.2 HDR4.9 HDR4.10 J1.2 J1.3 J2.5 J2.10 J2.11 J3.5 J3.6 J3.7 J3.8 J3.10 J3.16 J3.17 JP1.6 JP1.21 JP1.22 JP1.23 JP1.24 JP1.25 JP1.42 LCD1.1 Q1.2 R5.2 R10.1 R17.2 R19.2 R20.2 R39.1 SW5.3 SW5.4 U1.1 U1.12 U1.19 U1.25 U1.32 U1.39 U1.50 U1.51 U1.54 U1.65 U1.72 U1.79 U1.85 U1.92 U1.103 U1.117 U1.124 U1.131 U1.137 U1.144 U1.158 U1.170 U1.177 U1.183 U1.190 U1.197 U2.2 U3.10 U7.15 U8.9 U8.25 U9.9 U9.25 U10.11 U11.11 U12.4 VR1.CCW | length 1941.4
  Top Layer w7.87: v1(2170,3313.37) v1@2170.41,3313.37
  Top Layer w19.68: v1(2475,3700) 2487.4,3712.4 C3.2@2550,3712.4
  Top Layer w39.37: 3215.74,295.28 J1.3@3335,295.28 ; 3335,185 J1.3@3335,295.28 ; 3335,415 J1.3@3335,295.28 ; 3404.28,2015 C6.2@3460,2015 ; 3413.18,417.32 J1.2@3531.85,417.32 ; 3418.1,2815 C4.2@3460,2815 ; 3445.26,852.36 C13.2@3510,852.36 ; 3446.06,295.28 J1.3@3335,295.28 ; 3457.86,2768.24 3460,2770.37 C4.2@3460,2815 ; 3460,1952.14 C6.2@3460,2015 ; 3460,2072.44 C6.2@3460,2015 ; 3460,2856.16 C4.2@3460,2815 ; 3510,810 C13.2@3510,852.36 ; 3510,917.29 C13.2@3510,852.36 ; 3521.8,2015 C6.2@3460,2015 ; 3522.19,2815 C4.2@3460,2815 ; 3531.85,298.18 J1.2@3531.85,417.32 ; 3531.85,524.18 J1.2@3531.85,417.32 ; 3575.19,852.36 C13.2@3510,852.36 ; 3648.82,417.32 J1.2@3531.85,417.32 ; 3750.74,515 C5.2@3825,515 ; 3825,440.94 C5.2@3825,515 ; 3825,568.07 C5.2@3825,515 ; 3890,515 C5.2@3825,515
  Bottom Layer w7.87: v1@2550,4775 v1(2550,4779.51)
  other v1: 2300,180 2660,349.8 2295,612.98 1714.95,675 2630,882.28 2000,1136.61 2475,1140 2235,1181.49 2365,1181.49 2125,1188.97 2800,1286.21 2140,1325 2380,1325 2600,1325 1775,1331.09 2950,1580 1975,1600 2475,1600 1175,1607.86 1175,1675.19 2950,1680 2750,1720 1560,1725 1700,1725 2896.84,1820 2890,1935 1700,1975 2750,1980 1500,2000 2940,2095 1975,2100 2475,2101.56 1500,2120 2750,2285 1765,2375 2100,2375 2664.95,2375 2350,2380 1975,2500 2225,2500 2472.27,2500 2280,2615 625,2692.51 2290,2775 2238.57,3075 2300,3280 250,3750 2300,3792.11 700,3850 2150,3900 2440.54,4775 2125,4779.51 1575,6208.25 1300,6440.14 2250,6450 2625,6450 2975,6450 2500,6675 2800,6675
GREEN0: R32.1 U1.42 | length 4467.7
  Top Layer w7.87: R32.1@2452.6,6275 2452.6,5822.4 2750,5525 2750,5125 2750,3925 2925,3750 2925,2550 3000,2475 3000,2270 2885.12,2155.12 U1.42@2811.61,2155.12
GREEN1: R35.1 U1.43 | length 4602.2
  Top Layer w7.87: R35.1@2452.6,6375 2415,6375 2390,6350 2390,5860 2725,5525 2725,5125 2725,3925 2900,3750 2900,2550 2980,2470 2980,2275 2879.8,2174.8 U1.43@2811.61,2174.8
GSM_CTS: JP1.37 U1.146 | length 273.7
  Top Layer w7.87: JP1.37@1388.19,1488.19 1488.19,1488.19 1544.88,1544.88 U1.146@1638.39,1544.88
GSM_IGT: JP1.41 U1.147 | length 298.1
  Top Layer w7.87: JP1.41@1388.19,1409.45 1440.55,1409.45 1556.3,1525.2 U1.147@1638.39,1525.2
GSM_RTS: JP1.34 U1.145 | length 257.4
  Top Layer w7.87: JP1.34@1388.19,1547.24 1497.24,1547.24 1514.57,1564.57 U1.145@1638.39,1564.57
GSM_RXD: JP1.15 U1.126 | length 1124.3
  Top Layer w7.87: JP1.15@1246.46,1507.87 1117.13,1507.87 1050,1575 1050,1850 1138.58,1938.58 U1.126@1638.39,1938.58
GSM_SYNC: JP1.13 U1.125 | length 1213.4
  Top Layer w7.87: JP1.13@1246.46,1468.5 1106.5,1468.5 1025,1550 1025,1850 1133.27,1958.27 U1.125@1638.39,1958.27
GSM_TXD: JP1.17 U1.127 | length 1035.2
  Top Layer w7.87: JP1.17@1246.46,1547.24 1127.76,1547.24 1075,1600 1075,1850 1143.9,1918.9 U1.127@1638.39,1918.9
I\N\I\T\: R24.2 U1.107 U10.8 | length 3141.6
  Top Layer w7.87: v1(1625,2550) 1550,2475 1550,2350 1587.4,2312.6 U1.107@1638.39,2312.6 ; v1(2125,850) 2250,850 2262.4,837.6 R24.2@2262.4,800 2360,800 2386.02,826.02 U10.8@2386.02,884.25
  Bottom Layer w7.87: v1(1625,2550) 1325,2250 1325,1175 1650,850 v1(2125,850)
I\N\I\T\_\P\R\: R27.2 U1.201 U11.8 | length 2316.3
  Top Layer w7.87: U11.8@2386.02,434.25 2386.02,386.02 2375,375 R27.2@2237.4,375 2237.4,397.6 2200,435 2200,510 2190,520 2135,520 2125,510 2125,240 2135,230 2265,230 2267.73,230 2280,242.27 2280,265 2340,325 2550,325 2625,400 2625,525 2800,700 2800,850 2589.17,1060.83 U1.201@2589.17,1263.39
JTAG_NEXUS_TCK: HDR4.7 RA4.3 U1.164 | length 1155
  Top Layer w7.87: HDR4.7@1725,250 1725,300 1675,350 1675,475 1700,500 RA4.3@1737,500 1775,500 1800,525 1800,625 1860.83,685.83 U1.164@1860.83,1263.39
JTAG_NEXUS_TDI: HDR4.5 RA4.1 U1.166 | length 1132.5
  Top Layer w7.87: RA4.1@1737,400 1825,400 ; HDR4.5@1825,250 1825,400 ; U1.166@1900.2,1263.39 1900.2,675.2 1850,625 1850,425 1825,400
